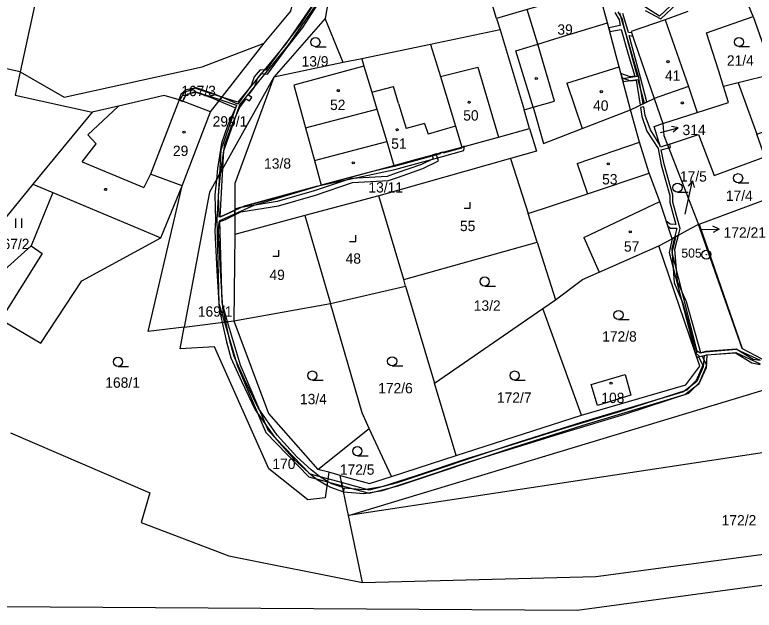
# Model space of a CAD drawing. Extents: x -779723 to -777378, y -1011169 to -1009297.
# Drawn here: x -779222.9 to -779101.4, y -1010475 to -1010377.1 of the extents above; entities that cross this region are included whole.
import ezdxf

# ---------------------------------------------------------------- set-up
doc = ezdxf.new("R2010")
doc.units = 0
for name, color, linetype in [('Hranice parcel', 7, 'Continuous'), ('Parcelní čísla', 7, 'Continuous'), ('Pop  PČ popisy', 7, 'Continuous'), ('Poz předměty', 7, 'Continuous'), ('Vnitřní kresba', 7, 'Continuous'), ('Věcná břemena k části', 7, 'Continuous'), ('Značky bodu BP', 7, 'Continuous'), ('Značky budov', 7, 'Continuous'), ('Značky kultur', 7, 'Continuous')]:
    doc.layers.add(name, color=color, linetype=linetype)

msp = doc.modelspace()

# ---------------------------------------------------------------- linework, layer by layer
at = {"layer": 'Hranice parcel'}
for p, q in [((-779143.7, -1010377.71), (-779148.14, -1010362.87)), ((-779170.69, -1010370.7), (-779171.88, -1010377.7)), ((-779125.49, -1010378.42), (-779126.96, -1010372.9)), ((-779171.88, -1010377.7), (-779180.32, -1010387.37)), ((-779168.93, -1010384.98), (-779171.88, -1010377.7)), ((-779143.7, -1010377.71), (-779143.14, -1010379.58)), ((-779101.55, -1010377.4), (-779098.22, -1010386.86)), ((-779143.14, -1010379.58), (-779154.57, -1010381.98)), ((-779143.14, -1010379.58), (-779139.2, -1010392.75)), ((-779190.77, -1010393.08), (-779181.94, -1010381.76)), ((-779154.57, -1010381.98), (-779165.87, -1010384.34)), ((-779222.02, -1010386.49), (-779237.61, -1010383.13)), ((-779165.87, -1010384.34), (-779168.93, -1010384.98)), ((-779165.87, -1010384.34), (-779165.53, -1010385.55)), ((-779168.93, -1010384.98), (-779180.32, -1010387.37)), ((-779106.38, -1010388.93), (-779107.15, -1010386.41)), ((-779121.71, -1010392.72), (-779117.8, -1010390.87)), ((-779117.8, -1010390.87), (-779116.39, -1010395)), ((-779139.2, -1010392.75), (-779137.7, -1010392.32)), ((-779138.27, -1010395.83), (-779139.2, -1010392.75)), ((-779210.18, -1010393.14), (-779219.94, -1010404.96)), ((-779195.38, -1010405.25), (-779190.77, -1010393.08)), ((-779117.81, -1010395.46), (-779116.39, -1010395)), ((-779116.39, -1010395), (-779116.19, -1010396.96)), ((-779116.19, -1010396.96), (-779115.59, -1010398.51)), ((-779115.59, -1010398.51), (-779110.52, -1010411.6)), ((-779141.41, -1010400.75), (-779163.08, -1010406.87)), ((-779141.41, -1010400.75), (-779138.52, -1010409.8)), ((-779172.54, -1010405.15), (-779160.58, -1010401.9)), ((-779186.75, -1010409.02), (-779172.54, -1010405.15)), ((-779110.38, -1010411.52), (-779091.99, -1010404.73)), ((-779163.08, -1010406.87), (-779175.21, -1010410.13)), ((-779158.98, -1010420.63), (-779163.08, -1010406.87)), ((-779186.75, -1010409.02), (-779186.75, -1010413.24)), ((-779137.02, -1010414.51), (-779138.52, -1010409.8)), ((-779175.21, -1010410.13), (-779186.75, -1010413.24)), ((-779175.21, -1010410.13), (-779171.02, -1010424.6)), ((-779110.52, -1010411.6), (-779110.38, -1010411.52)), ((-779110.38, -1010411.52), (-779103.35, -1010431.99)), ((-779186.75, -1010413.24), (-779186.88, -1010427.45)), ((-779158.98, -1010420.63), (-779137.02, -1010414.51)), ((-779137.02, -1010414.51), (-779134, -1010424)), ((-779117.03, -1010415.13), (-779114.86, -1010413.95)), ((-779231.29, -1010425.07), (-779220.25, -1010415.13)), ((-779158.66, -1010421.72), (-779158.98, -1010420.63)), ((-779171.02, -1010424.6), (-779158.66, -1010421.72)), ((-779158.66, -1010421.72), (-779153.92, -1010437.67)), ((-779186.88, -1010427.45), (-779171.02, -1010424.6)), ((-779136.09, -1010425.43), (-779134, -1010424)), ((-779153.92, -1010437.67), (-779136.09, -1010425.43)), ((-779129.76, -1010442.93), (-779136.09, -1010425.43)), ((-779195.06, -1010428.47), (-779186.88, -1010427.45)), ((-779168.06, -1010459.43), (-779063.54, -1010427.85)), ((-779150.37, -1010449.59), (-779153.92, -1010437.67)), ((-779150.37, -1010449.59), (-779129.76, -1010442.93)), ((-779173.08, -1010451.87), (-779164.63, -1010445.15)), ((-779161.01, -1010453.02), (-779164.63, -1010445.15)), ((-779161.01, -1010453.02), (-779150.37, -1010449.59)), ((-779171.3, -1010452.35), (-779173.08, -1010451.87)), ((-779169.43, -1010452.86), (-779171.3, -1010452.35)), ((-779168.06, -1010459.43), (-779169.43, -1010452.86)), ((-779165.75, -1010470.45), (-779168.06, -1010459.43))]:
    msp.add_line(p, q, dxfattribs=at)
for points in [[(-779204.93, -1010344.94), (-779217.76, -1010366.81), (-779222.02, -1010386.49)], [(-779181.94, -1010381.76), (-779177.51, -1010376.54), (-779174.51, -1010363.75)], [(-779126.96, -1010372.9), (-779138.68, -1010376.27), (-779143.7, -1010377.71)], [(-779101.55, -1010377.4), (-779102.69, -1010374.53), (-779102.81, -1010374.14)], [(-779112.28, -1010376.55), (-779116, -1010377.97), (-779121.56, -1010379.84), (-779120.97, -1010381.67), (-779117.8, -1010390.87)], [(-779137.7, -1010392.32), (-779140.53, -1010383.03), (-779136.94, -1010381.93), (-779134.12, -1010381.07), (-779125.49, -1010378.42)], [(-779121.71, -1010392.72), (-779123.54, -1010385.7), (-779124.04, -1010383.84), (-779125.49, -1010378.42)], [(-779107.15, -1010386.41), (-779109.18, -1010380.08), (-779101.55, -1010377.4)], [(-779222.02, -1010386.49), (-779214.8, -1010390.67), (-779192.12, -1010385.68), (-779181.94, -1010381.76)], [(-779154.57, -1010381.98), (-779152.95, -1010387.28), (-779150.45, -1010395.45), (-779149.41, -1010398.86)], [(-779165.53, -1010385.55), (-779177.07, -1010388.7), (-779175.14, -1010395.73), (-779173.66, -1010401.1), (-779172.54, -1010405.15)], [(-779165.53, -1010385.55), (-779164.23, -1010389.85), (-779163.38, -1010392.66), (-779162.54, -1010395.42), (-779161.78, -1010397.93), (-779160.58, -1010401.9)], [(-779222.02, -1010386.49), (-779222.86, -1010390.35), (-779210.18, -1010393.14)], [(-779098.22, -1010386.86), (-779103.99, -1010388.3), (-779106.38, -1010388.93)], [(-779180.32, -1010387.37), (-779190.91, -1010406.29), (-779195.06, -1010428.47)], [(-779180.32, -1010387.37), (-779186.74, -1010404.87), (-779186.75, -1010409.02)], [(-779116.39, -1010395), (-779110.74, -1010393.18), (-779105.6, -1010391.53), (-779106.38, -1010388.93)], [(-779190.77, -1010393.08), (-779195.92, -1010391.11), (-779198.36, -1010390.38), (-779205.88, -1010392.14), (-779210.18, -1010393.14)], [(-779137.7, -1010392.32), (-779136.01, -1010398.29), (-779129.66, -1010395.82), (-779121.71, -1010392.72)], [(-779118.64, -1010403.14), (-779120.21, -1010398.06), (-779121.71, -1010392.72)], [(-779115.59, -1010398.51), (-779110.51, -1010396.79), (-779107.93, -1010403.57), (-779099.61, -1010400.48), (-779100.91, -1010396.73), (-779095.45, -1010394.78)], [(-779149.41, -1010398.86), (-779143.38, -1010397.22), (-779138.27, -1010395.83)], [(-779138.27, -1010395.83), (-779137.16, -1010399.54), (-779141.41, -1010400.75)], [(-779115.59, -1010398.51), (-779116.75, -1010398.9), (-779117.81, -1010395.46)], [(-779160.58, -1010401.9), (-779157.03, -1010400.93), (-779149.41, -1010398.86)], [(-779138.52, -1010409.8), (-779134.68, -1010408.52), (-779128.76, -1010406.55), (-779118.64, -1010403.14)], [(-779114.86, -1010413.95), (-779116.88, -1010407.82), (-779118.64, -1010403.14)], [(-779219.94, -1010404.96), (-779226.66, -1010413.11), (-779231.29, -1010425.07)], [(-779219.94, -1010404.96), (-779216.67, -1010406.33), (-779220.25, -1010415.13)], [(-779220.25, -1010415.13), (-779218.42, -1010416.38), (-779225.24, -1010427.24), (-779218.62, -1010431.11), (-779211.9, -1010420.85), (-779198.89, -1010413.78), (-779195.38, -1010405.25)], [(-779195.06, -1010428.47), (-779201, -1010429.21), (-779195.38, -1010405.25)], [(-779110.52, -1010411.6), (-779111.87, -1010412.33), (-779114.86, -1010413.95)], [(-779103.35, -1010431.99), (-779110.28, -1010412.21), (-779110.52, -1010411.6)], [(-779134, -1010424), (-779129.59, -1010420.64), (-779126.85, -1010419.42), (-779117.03, -1010415.13)], [(-779129.76, -1010442.93), (-779112.61, -1010437.99), (-779110.3, -1010434.92), (-779117.03, -1010415.13)], [(-779164.63, -1010445.15), (-779165.83, -1010442.55), (-779171.02, -1010424.6)], [(-779186.88, -1010427.45), (-779181.22, -1010442.66), (-779173.08, -1010451.87)], [(-779171.3, -1010452.35), (-779171.87, -1010456.53), (-779174.76, -1010456.86), (-779181.17, -1010451.77), (-779190.11, -1010431.7), (-779195.73, -1010432.05), (-779195.06, -1010428.47)], [(-779103.35, -1010431.99), (-779100.12, -1010433.69), (-779083.42, -1010428.77)], [(-779122.59, -1010436.25), (-779121.63, -1010439.67), (-779127.13, -1010441.39), (-779128.15, -1010437.89), (-779122.59, -1010436.25)], [(-779223.61, -1010445.86), (-779200.73, -1010455.74), (-779202.13, -1010460.62), (-779187.71, -1010466.11), (-779165.75, -1010470.45)], [(-779030.17, -1010449.35), (-779043.03, -1010446.43), (-779084.08, -1010446.73), (-779168.06, -1010459.43)], [(-779165.75, -1010470.45), (-779127.38, -1010469.51), (-779070.54, -1010461.9), (-779035.24, -1010455.28), (-779030.17, -1010449.35)], [(-779169.43, -1010452.86), (-779164.59, -1010454.17), (-779161.01, -1010453.02)]]:
    msp.add_lwpolyline(points, dxfattribs=at)
at = {"layer": 'Pop  PČ popisy'}
for p, q in [((-779116.76, -1010396.47), (-779113.86, -1010395.69)), ((-779113.86, -1010395.69), (-779114.96, -1010395.47)), ((-779113.86, -1010395.69), (-779114.7, -1010396.44)), ((-779111.52, -1010404.43), (-779112.21, -1010405.3)), ((-779112.14, -1010407.36), (-779111.52, -1010404.43)), ((-779111.52, -1010404.43), (-779111.23, -1010405.51)), ((-779112.71, -1010409.91), (-779112.14, -1010407.36)), ((-779110.13, -1010412.43), (-779107.13, -1010412.38)), ((-779107.13, -1010412.38), (-779108.14, -1010411.89)), ((-779107.13, -1010412.38), (-779108.12, -1010412.9))]:
    msp.add_line(p, q, dxfattribs=at)
at = {"layer": 'Poz předměty'}
for p, q in [((-779130.44, -1010475.03), (-779042.85, -1010463.08)), ((-779395.56, -1010473.38), (-779130.44, -1010475.03))]:
    msp.add_line(p, q, dxfattribs=at)
at = {"layer": 'Vnitřní kresba'}
for p, q in [((-779136.94, -1010381.93), (-779138.68, -1010376.27)), ((-779116, -1010377.97), (-779112.15, -1010388.92)), ((-779134.17, -1010391.31), (-779136.94, -1010381.93)), ((-779152.95, -1010387.28), (-779146.78, -1010385.72)), ((-779146.78, -1010385.72), (-779143.38, -1010397.22)), ((-779132.14, -1010388.34), (-779123.54, -1010385.7)), ((-779164.23, -1010389.85), (-779160.66, -1010388.9)), ((-779159.81, -1010391.73), (-779160.66, -1010388.9)), ((-779132.14, -1010388.34), (-779129.66, -1010395.82)), ((-779112.15, -1010388.92), (-779117.8, -1010390.87)), ((-779112.15, -1010388.92), (-779110.74, -1010393.18)), ((-779103.99, -1010388.3), (-779100.91, -1010396.73)), ((-779195.92, -1010391.11), (-779200.6, -1010403.31)), ((-779159.81, -1010391.73), (-779159.01, -1010394.4)), ((-779137.7, -1010392.32), (-779134.17, -1010391.31)), ((-779210.93, -1010396.85), (-779205.88, -1010392.14)), ((-779175.14, -1010395.73), (-779163.38, -1010392.66)), ((-779159.01, -1010394.4), (-779158.58, -1010395.81)), ((-779155.55, -1010395), (-779158.58, -1010395.81)), ((-779155.55, -1010395), (-779154.97, -1010396.76)), ((-779150.45, -1010395.45), (-779154.97, -1010396.76)), ((-779210.93, -1010396.85), (-779209.53, -1010398.31)), ((-779211.82, -1010401.29), (-779209.53, -1010398.31)), ((-779173.66, -1010401.1), (-779161.78, -1010397.93)), ((-779130.48, -1010401.56), (-779120.21, -1010398.06)), ((-779211.82, -1010401.29), (-779201.69, -1010405.54)), ((-779130.48, -1010401.56), (-779128.76, -1010406.55)), ((-779200.6, -1010403.31), (-779201.69, -1010405.54)), ((-779195.38, -1010405.25), (-779200.6, -1010403.31)), ((-779216.67, -1010406.33), (-779198.89, -1010413.78)), ((-779129.37, -1010413.73), (-779116.88, -1010407.82)), ((-779129.37, -1010413.73), (-779126.85, -1010419.42))]:
    msp.add_line(p, q, dxfattribs=at)
at = {"layer": 'Věcná břemena k části'}
for points in [[(-779168.84, -1010359.9), (-779168.74, -1010359.3), (-779169.22, -1010359.65), (-779170.31, -1010366.86), (-779171.63, -1010372.03), (-779178.35, -1010381.89), (-779186.23, -1010391.51), (-779188.9, -1010390.68), (-779189.2, -1010391.07), (-779186.47, -1010391.96), (-779189.03, -1010399.39), (-779189.26, -1010403.35), (-779188.7, -1010402.34), (-779188.53, -1010399.49), (-779185.93, -1010391.92), (-779177.95, -1010382.19), (-779171.17, -1010372.23), (-779170.69, -1010370.7)], [(-779189.35, -1010391.25), (-779188.9, -1010390.68), (-779190.38, -1010390.04), (-779193.09, -1010389.13), (-779194.77, -1010389.43), (-779195.64, -1010390.24), (-779195.95, -1010391.1), (-779195.28, -1010391.36), (-779195.04, -1010390.64), (-779194.45, -1010390.09), (-779193.15, -1010389.85), (-779190.64, -1010390.7)], [(-779189.2, -1010391.07), (-779188.9, -1010390.68), (-779193.34, -1010389.18), (-779195.14, -1010389.97), (-779195.79, -1010391.16), (-779195.28, -1010391.36), (-779194.78, -1010390.35), (-779193.32, -1010389.72)], [(-779120.07, -1010392.38), (-779119.85, -1010393.85), (-779118.98, -1010396.24), (-779117.17, -1010399.09), (-779116.65, -1010401.77), (-779115.24, -1010406.81), (-779115.2, -1010407.99), (-779114.25, -1010411.58), (-779115.18, -1010411.53), (-779115.82, -1010411.05), (-779115.54, -1010411.88), (-779115.09, -1010412.23), (-779114.05, -1010412.21), (-779114.44, -1010413.72), (-779113.81, -1010413.38), (-779113.51, -1010412.24), (-779113.71, -1010411.73), (-779114.72, -1010407.94), (-779114.75, -1010406.76), (-779116.18, -1010401.66), (-779116.63, -1010399.3), (-779115.39, -1010399.01), (-779115.12, -1010398.95), (-779115.25, -1010398.39), (-779115.59, -1010398.51), (-779116.75, -1010398.9), (-779116.87, -1010398.52), (-779118.4, -1010396.06), (-779119.29, -1010393.65), (-779119.52, -1010392.26)], [(-779149.09, -1010399.45), (-779148.96, -1010398.74), (-779149.41, -1010398.86), (-779149.49, -1010399.05), (-779152.51, -1010399.87), (-779152.55, -1010399.71), (-779153.03, -1010399.84), (-779152.99, -1010400), (-779156.94, -1010401.07), (-779160.55, -1010402.06), (-779164.33, -1010402.92), (-779172.54, -1010405.15), (-779160.42, -1010402.54), (-779156.8, -1010401.55), (-779152.62, -1010400.42)], [(-779153.26, -1010401.13), (-779153.62, -1010400), (-779154.32, -1010400.19), (-779154.14, -1010400.78), (-779156.07, -1010401.73), (-779160.21, -1010403.16), (-779161.68, -1010403.69), (-779167.63, -1010404.02), (-779173.69, -1010406.07), (-779179.78, -1010407.84), (-779186.02, -1010408.86), (-779186.75, -1010409.22), (-779186.75, -1010410), (-779185.74, -1010409.5), (-779179.56, -1010408.53), (-779173.49, -1010406.76), (-779167.4, -1010404.71), (-779161.47, -1010404.37), (-779160.01, -1010403.85), (-779155.83, -1010402.41)], [(-779186.75, -1010409.84), (-779186.75, -1010409.29), (-779189.18, -1010410.37), (-779188.7, -1010402.34), (-779189.26, -1010403.35), (-779189.7, -1010410.77), (-779189.35, -1010424.59), (-779188.44, -1010427.64), (-779187.94, -1010427.58), (-779188.85, -1010424.51), (-779189.2, -1010410.93)], [(-779186.75, -1010410), (-779186.75, -1010409.22), (-779188.58, -1010410.13), (-779189.31, -1010410.39), (-779189.43, -1010406.74), (-779189.02, -1010402.91), (-779189.77, -1010404.25), (-779190.03, -1010406.72), (-779189.9, -1010410.87), (-779190.01, -1010412.68), (-779189.71, -1010419.14), (-779189.32, -1010425.44), (-779188.83, -1010427.69), (-779188.23, -1010427.62), (-779188.72, -1010425.36), (-779189.11, -1010419.1), (-779189.41, -1010412.68), (-779189.32, -1010411.14), (-779188.3, -1010410.77)], [(-779183.56, -1010408.43), (-779173.13, -1010405.31), (-779185.19, -1010408.59), (-779186.75, -1010409.29), (-779186.75, -1010409.84)], [(-779169.01, -1010454.87), (-779170.77, -1010454.27), (-779171.5, -1010453.84), (-779172.84, -1010453.05), (-779174.2, -1010451.97), (-779176.57, -1010449.83), (-779179.76, -1010446.22), (-779182.88, -1010441.77), (-779185.13, -1010437.09), (-779186.86, -1010433.33), (-779187.55, -1010430.75), (-779188.23, -1010427.62), (-779188.83, -1010427.69), (-779188.13, -1010430.89), (-779187.42, -1010433.53), (-779185.67, -1010437.35), (-779183.4, -1010442.07), (-779180.24, -1010446.6), (-779176.99, -1010450.25), (-779174.58, -1010452.43), (-779173.18, -1010453.55), (-779171.59, -1010454.48), (-779171.03, -1010454.81), (-779168.87, -1010455.54)], [(-779169.18, -1010454.05), (-779171.45, -1010453.44), (-779174.33, -1010452.67), (-779181.22, -1010445.54), (-779185.81, -1010434.73), (-779187.94, -1010427.58), (-779188.44, -1010427.64), (-779186.28, -1010434.89), (-779181.64, -1010445.82), (-779174.59, -1010453.11), (-779171.52, -1010453.94), (-779169.07, -1010454.6)]]:
    msp.add_lwpolyline(points, close=True, dxfattribs=at)
for points in [[(-779172.59, -1010373.48), (-779176.06, -1010378.84), (-779178.69, -1010382.2), (-779181.66, -1010386.24), (-779182.6, -1010386.17), (-779183.57, -1010387.31), (-779184.05, -1010388.72), (-779185.17, -1010390.27), (-779185.54, -1010390.79), (-779186.27, -1010391.81), (-779188.9, -1010390.68), (-779189.35, -1010391.25), (-779186.62, -1010392.42), (-779187.93, -1010395.39), (-779188.96, -1010398.24), (-779189.57, -1010402.4), (-779189.77, -1010404.25), (-779189.02, -1010402.91), (-779188.97, -1010402.48), (-779188.38, -1010398.38), (-779187.37, -1010395.61), (-779185.96, -1010392.41), (-779184.89, -1010390.91), (-779184.35, -1010391.29), (-779183.94, -1010390.72), (-779184.48, -1010390.34), (-779183.51, -1010389), (-779183.03, -1010387.61), (-779182.34, -1010386.79), (-779181.38, -1010386.86), (-779178.21, -1010382.56), (-779175.58, -1010379.18), (-779172.09, -1010373.8)], [(-779114.29, -1010374.86), (-779116.91, -1010377.35), (-779119.33, -1010375.83)], [(-779119.27, -1010376.39), (-779116.7, -1010377.8), (-779114.02, -1010375.27)], [(-779124.28, -1010376.76), (-779123.56, -1010377.92), (-779123.39, -1010378.88), (-779125.27, -1010379.24), (-779125.1, -1010379.89), (-779123.23, -1010379.54), (-779122.05, -1010383.61), (-779120.97, -1010387.22), (-779121.73, -1010387.32), (-779123.26, -1010386.79), (-779123.07, -1010387.51), (-779121.69, -1010387.99), (-779120.76, -1010387.87), (-779120.13, -1010391.97), (-779119.61, -1010391.72), (-779120.3, -1010387.47), (-779121.48, -1010383.56), (-779122.76, -1010379.14), (-779122.99, -1010377.81), (-779123.73, -1010376.61)], [(-779123.51, -1010376.79), (-779122.46, -1010380.32), (-779120.6, -1010387.29), (-779123.03, -1010387.64), (-779122.91, -1010388.11), (-779120.48, -1010387.76), (-779119.45, -1010391.65), (-779119.01, -1010391.44), (-779120.07, -1010387.43), (-779121.9, -1010380.54), (-779121.31, -1010380.62), (-779121.47, -1010380.11), (-779122.04, -1010380.04), (-779122.96, -1010376.93)], [(-779100.31, -1010433.95), (-779104.28, -1010432.17), (-779109.34, -1010432.57), (-779110.22, -1010432.77), (-779110.72, -1010432.41), (-779114.82, -1010416.18), (-779114.3, -1010414), (-779114.28, -1010413.63), (-779114.86, -1010413.95), (-779115.32, -1010416.19), (-779111.07, -1010432.64), (-779110.34, -1010433.31), (-779109.57, -1010433.14), (-779109.72, -1010435.02), (-779110.81, -1010437.42), (-779112.99, -1010439.11), (-779129.64, -1010444.12), (-779141.2, -1010447.79), (-779160.04, -1010454.1), (-779164.66, -1010455.27), (-779169.18, -1010454.05), (-779169.07, -1010454.6), (-779164.66, -1010455.79), (-779159.9, -1010454.58), (-779141.04, -1010448.27), (-779129.5, -1010444.6), (-779112.75, -1010439.57), (-779110.41, -1010437.74), (-779109.22, -1010435.14), (-779109.07, -1010433.05), (-779104.36, -1010432.67), (-779100.35, -1010434.49)], [(-779100.38, -1010433.99), (-779101.52, -1010433.78), (-779104.31, -1010432.11), (-779109.28, -1010432.46), (-779110.14, -1010432.68), (-779112.51, -1010424.32), (-779113.96, -1010421), (-779114.4, -1010415.64), (-779113.81, -1010413.38), (-779114.44, -1010413.72), (-779114.92, -1010415.62), (-779114.52, -1010421.22), (-779113.07, -1010424.52), (-779110.77, -1010432.66), (-779111.07, -1010432.64), (-779110.83, -1010433.36), (-779110.51, -1010433.38), (-779109.79, -1010434.75), (-779110.87, -1010437.23), (-779112.43, -1010438.83), (-779122.78, -1010442.21), (-779132.84, -1010445.2), (-779141.15, -1010447.81), (-779148.6, -1010450.11), (-779157.09, -1010452.97), (-779162.59, -1010454.74), (-779165.54, -1010455.23), (-779168.8, -1010454.94), (-779168.87, -1010455.54), (-779165.52, -1010455.83), (-779162.45, -1010455.32), (-779156.91, -1010453.55), (-779148.42, -1010450.69), (-779140.97, -1010448.39), (-779132.66, -1010445.78), (-779122.6, -1010442.79), (-779112.11, -1010439.35), (-779110.37, -1010437.57), (-779109.13, -1010434.73), (-779109.91, -1010433.24), (-779109.18, -1010433.06), (-779104.45, -1010432.73), (-779101.74, -1010434.34), (-779100.36, -1010434.61)]]:
    msp.add_lwpolyline(points, dxfattribs=at)
at = {"layer": 'Značky bodu BP'}
for radius in [0.75, 0.03]:
    msp.add_circle((-779109.23, -1010416.55), radius, dxfattribs=at)
at = {"layer": 'Značky budov'}
for centre in [(-779115.52, -1010384.83), (-779137.18, -1010387.58), (-779169.74, -1010389.58), (-779126.49, -1010389.76), (-779148.21, -1010391.5), (-779113.17, -1010391.61), (-779195.09, -1010396.43), (-779160.05, -1010396.02), (-779167.27, -1010401.46), (-779125.35, -1010401.62), (-779207.99, -1010405.83), (-779121.73, -1010412.81), (-779124.89, -1010437.7)]:
    msp.add_circle(centre, 0.175, dxfattribs=at)
at = {"layer": 'Značky kultur'}
for p, q in [((-779173.49, -1010382.36), (-779171.74, -1010382.36)), ((-779103.86, -1010382.35), (-779102.11, -1010382.35)), ((-779104, -1010404.74), (-779102.25, -1010404.74)), ((-779113.96, -1010406.29), (-779112.21, -1010406.29)), ((-779148.03, -1010408.91), (-779148.03, -1010407.91)), ((-779149.03, -1010408.91), (-779148.03, -1010408.91)), ((-779222.76, -1010412.13), (-779222.76, -1010410.63)), ((-779221.76, -1010412.13), (-779221.76, -1010410.63)), ((-779166.87, -1010414.38), (-779166.87, -1010413.38)), ((-779167.87, -1010414.38), (-779166.87, -1010414.38)), ((-779179.52, -1010416.82), (-779179.52, -1010415.82)), ((-779180.52, -1010416.82), (-779179.52, -1010416.82)), ((-779145.66, -1010421.73), (-779143.91, -1010421.73)), ((-779123.66, -1010427.22), (-779121.91, -1010427.22)), ((-779205.95, -1010434.93), (-779204.2, -1010434.93)), ((-779160.88, -1010434.85), (-779159.13, -1010434.85)), ((-779173.99, -1010437.19), (-779172.24, -1010437.19)), ((-779140.74, -1010437.19), (-779138.99, -1010437.19)), ((-779166.59, -1010449.62), (-779164.84, -1010449.62))]:
    msp.add_line(p, q, dxfattribs=at)
for centre in [(-779173.49, -1010381.61), (-779103.86, -1010381.6), (-779104, -1010403.99), (-779113.96, -1010405.54), (-779145.66, -1010420.98), (-779123.66, -1010426.47), (-779205.95, -1010434.18), (-779160.88, -1010434.1), (-779173.99, -1010436.44), (-779140.74, -1010436.44), (-779166.59, -1010448.87)]:
    msp.add_circle(centre, 0.75, dxfattribs=at)

# ---------------------------------------------------------------- texts
at = {"layer": 'Parcelní čísla'}
for s, p in [('39', (-779133.71, -1010380.39)), ('13/9', (-779175.77, -1010385.62)), ('21/4', (-779105.84, -1010385.48)), ('41', (-779116.02, -1010387.96)), ('167/3', (-779195.55, -1010390.49)), ('52', (-779171.09, -1010392.78)), ('40', (-779127.84, -1010392.89)), ('50', (-779149.19, -1010394.51)), ('299/1', (-779190.39, -1010395.49)), ('314', (-779113.14, -1010396.9)), ('51', (-779161.03, -1010399.15)), ('29', (-779196.92, -1010400.33)), ('13/8', (-779181.93, -1010402.42)), ('53', (-779126.36, -1010405.01)), ('17/5', (-779113.57, -1010404.55)), ('13/11', (-779164.78, -1010406.34)), ('17/4', (-779106.02, -1010407.72)), ('55', (-779149.73, -1010412.69)), ('172/21', (-779106.38, -1010413.77)), ('167/2', (-779226.2, -1010415.65)), ('57', (-779122.77, -1010416.07)), ('48', (-779168.53, -1010418.05)), ('49', (-779181.05, -1010420.73)), ('13/2', (-779147.46, -1010425.79)), ('169/1', (-779192.83, -1010426.76)), ('172/8', (-779126.35, -1010430.86)), ('168/1', (-779208.04, -1010438.45)), ('172/6', (-779163.18, -1010439.36)), ('172/7', (-779143.65, -1010440.91)), ('13/4', (-779176.03, -1010441.15)), ('108', (-779126.49, -1010440.96)), ('170', (-779180.57, -1010451.81)), ('172/5', (-779169.48, -1010452.75)), ('172/2', (-779106.7, -1010461.08))]:
    msp.add_text(s, height=1.7, dxfattribs=at).set_placement(p)
at = {"layer": 'Značky bodu BP'}
msp.add_text('505', height=1.5, dxfattribs=at).set_placement((-779113.33, -1010417.05))

doc.saveas('drawing.dxf')
